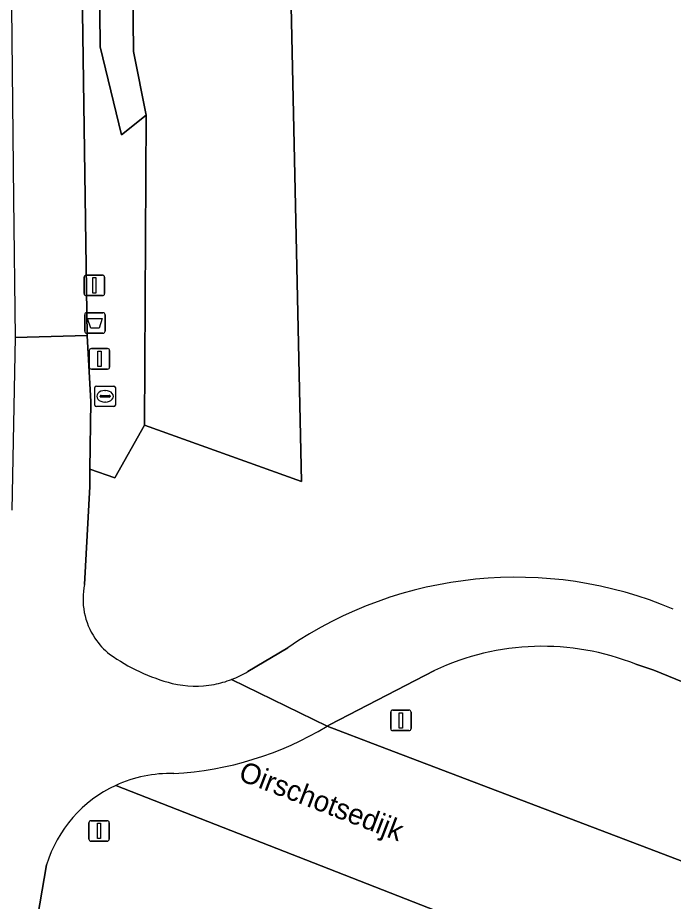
# Model space of a CAD drawing. Extents: x 155209 to 156748, y 385356 to 388487.
# Drawn here: x 155383.28 to 155415.19, y 386855.08 to 386898.09 of the extents above; entities that cross this region are included whole.
import ezdxf

# ---------------------------------------------------------------- set-up
doc = ezdxf.new("R2010")
doc.units = 0
for name, color, linetype in [('IMGEO_Afvalbak', 7, 'Continuous'), ('IMGEO_Berm_groen', 7, 'Continuous'), ('IMGEO_Fietspad_gesloten', 7, 'Continuous'), ('IMGEO_Groenvoorziening', 7, 'Continuous'), ('IMGEO_Lichtmast', 7, 'Continuous'), ('IMGEO_Openbare_ruimte_label', 7, 'Continuous'), ('IMGEO_Rijbaan_lokaal_gesloten', 7, 'Continuous'), ('IMGEO_Rioolput', 7, 'Continuous'), ('IMGEO_Verkeersbordpaal', 7, 'Continuous'), ('IMGEO_Waterloop', 7, 'Continuous')]:
    doc.layers.add(name, color=color, linetype=linetype)

msp = doc.modelspace()

# ---------------------------------------------------------------- linework, layer by layer
at = {"layer": 'IMGEO_Afvalbak'}
for p, q in [((155386.544, 386882.829), (155386.544, 386883.629)), ((155386.544, 386883.629), (155386.544, 386882.829)), ((155386.644, 386883.729), (155387.434, 386883.729)), ((155387.434, 386883.729), (155386.644, 386883.729)), ((155387.534, 386883.629), (155387.534, 386882.829)), ((155387.534, 386882.829), (155387.534, 386883.629)), ((155387.434, 386882.729), (155386.644, 386882.729)), ((155386.644, 386882.729), (155387.434, 386882.729))]:
    msp.add_line(p, q, dxfattribs=at)
msp.add_lwpolyline([(155386.687, 386883.443), (155387.391, 386883.443), (155387.242, 386882.973), (155386.836, 386882.973), (155386.687, 386883.443)], dxfattribs=at)
for centre, start, end in [((155386.644, 386883.629), 90, 180), ((155386.644, 386883.629), 90, 180), ((155387.434, 386883.629), 0, 90), ((155387.434, 386883.629), 360, 90), ((155386.644, 386882.829), 180, 270), ((155386.644, 386882.829), 180, 270), ((155387.434, 386882.829), 270, 0), ((155387.434, 386882.829), 270, 0)]:
    msp.add_arc(centre, 0.1, start, end, dxfattribs=at)
at = {"layer": 'IMGEO_Berm_groen'}
for points in [[(155418.719, 386864.507), (155414.232, 386866.333), (155413.361, 386866.621)], [(155403.572, 386866.316), (155398.462, 386863.678), (155398.335, 386863.601), (155400.892, 386862.631), (155414.712, 386857.387), (155445.113, 386845.774), (155457.912, 386840.913), (155464.072, 386841.781), (155467.301, 386844.699)]]:
    msp.add_lwpolyline(points, dxfattribs=at)
msp.add_arc((155408.816, 386855.242), 12.253, 68.2278, 115.3414, dxfattribs=at)
at = {"layer": 'IMGEO_Fietspad_gesloten'}
for points in [[(155382.435, 386951.848), (155382.988, 386898.593), (155383.085, 386889.277), (155383.155, 386882.53), (155386.663, 386882.616), (155385.603, 386955.738)], [(155386.535, 386870.503), (155386.79, 386875.274), (155386.801, 386876.114), (155386.843, 386879.394), (155386.663, 386882.616), (155383.155, 386882.53), (155383.002, 386874.113)], [(155396.425, 386867.426), (155394.487, 386866.267)], [(155413.361, 386866.621), (155414.232, 386866.333), (155418.719, 386864.507), (155466.767, 386846.51), (155472.836, 386844.21), (155476.035, 386842.963), (155485.347, 386839.199), (155494.869, 386835.35), (155500, 386833.173), (155528.28, 386821.173), (155542.082, 386815.316), (155582.645, 386799.402), (155644.455, 386774.959), (155657.253, 386770.116), (155663.892, 386767.514), (155664.942, 386770.249), (155650.373, 386775.842), (155597.752, 386796.796), (155542.238, 386818.668), (155529.413, 386824.073)], [(155393.692, 386865.88), (155398.335, 386863.601), (155398.462, 386863.678), (155403.572, 386866.316)], [(155398.335, 386863.601), (155393.692, 386865.88)], [(155383.299, 386848.707), (155384.694, 386856.865)]]:
    msp.add_lwpolyline(points, dxfattribs=at)
for centre, radius, start, end in [((155389.897, 386869.798), 3.435, 168.1555, 213.8152), ((155407.522, 386851.188), 19.668, 67.0661, 124.3484), ((155389.896, 386869.791), 3.43, 213.7329, 231.3216), ((155408.816, 386855.242), 12.253, 68.2278, 115.3414), ((155393.271, 386874.947), 9.583, 234.8348, 255.1048), ((155391.895, 386870.581), 5.033, 290.917, 300.996), ((155391.901, 386870.624), 5.071, 280.6868, 290.6876), ((155391.932, 386870.508), 4.951, 256.8808, 280.5831), ((155389.954, 386877.519), 16.247, 273.2741, 301.0545), ((155390.677, 386855.042), 6.261, 88.1205, 114.7565), ((155390.673, 386855.055), 6.247, 114.7756, 163.16)]:
    msp.add_arc(centre, radius, start, end, dxfattribs=at)
at = {"layer": 'IMGEO_Groenvoorziening'}
for points in [[(155388.32, 386952.733), (155388.915, 386896.442), (155389.537, 386893.35), (155389.459, 386878.251), (155397.089, 386875.516), (155395.168, 386964.319), (155388.717, 386966.803), (155386.235, 386964.989)], [(155536.098, 386910.335), (155534.286, 386910.986), (155527.745, 386913.58), (155523.099, 386915.056), (155395.168, 386964.319), (155397.089, 386875.516), (155389.459, 386878.251), (155388.004, 386875.687), (155386.801, 386876.114), (155386.79, 386875.274), (155386.535, 386870.503)], [(155385.413, 386956.748), (155385.603, 386955.738), (155386.663, 386882.616), (155386.843, 386879.394), (155386.801, 386876.114), (155388.004, 386875.687), (155389.459, 386878.251), (155389.537, 386893.35), (155388.34, 386892.391), (155387.298, 386896.672), (155386.781, 386950.846)], [(155394.487, 386866.267), (155396.425, 386867.426)], [(155394.977, 386847.885), (155396.121, 386848.772), (155399.255, 386850.072), (155401.499, 386850.438), (155406.884, 386849.679), (155433.798, 386839.395), (155443.335, 386836.339), (155453.576, 386832.241), (155454.34, 386830.99), (155455.729, 386830.445), (155457.34, 386833.958), (155453.658, 386835.338), (155447.01, 386837.973), (155422.593, 386847.21), (155388.055, 386860.727)], [(155384.694, 386856.865), (155383.299, 386848.707), (155377.495, 386814.325), (155376.591, 386809.635)]]:
    msp.add_lwpolyline(points, dxfattribs=at)
for centre, radius, start, end in [((155389.897, 386869.798), 3.435, 168.1555, 213.8152), ((155407.522, 386851.188), 19.668, 67.0661, 124.3484), ((155389.896, 386869.791), 3.43, 213.7329, 231.3216), ((155393.271, 386874.947), 9.583, 234.8348, 255.1048), ((155391.895, 386870.581), 5.033, 290.917, 300.996), ((155391.901, 386870.624), 5.071, 280.6868, 290.6876), ((155391.932, 386870.508), 4.951, 256.8808, 280.5831), ((155390.673, 386855.055), 6.247, 114.7756, 163.16)]:
    msp.add_arc(centre, radius, start, end, dxfattribs=at)
at = {"layer": 'IMGEO_Lichtmast'}
for p, q in [((155386.618, 386885.56), (155387.408, 386885.56)), ((155387.408, 386885.56), (155386.618, 386885.56)), ((155386.518, 386884.66), (155386.518, 386885.46)), ((155386.518, 386885.46), (155386.518, 386884.66)), ((155387.508, 386885.46), (155387.508, 386884.66)), ((155387.508, 386884.66), (155387.508, 386885.46)), ((155387.408, 386884.56), (155386.618, 386884.56)), ((155386.618, 386884.56), (155387.408, 386884.56)), ((155401.434, 386863.489), (155401.434, 386864.289)), ((155401.434, 386864.289), (155401.434, 386863.489)), ((155401.534, 386864.389), (155402.324, 386864.389)), ((155402.324, 386864.389), (155401.534, 386864.389)), ((155402.424, 386864.289), (155402.424, 386863.489)), ((155402.424, 386863.489), (155402.424, 386864.289)), ((155402.324, 386863.389), (155401.534, 386863.389)), ((155401.534, 386863.389), (155402.324, 386863.389)), ((155386.747, 386858.109), (155386.747, 386858.909)), ((155386.747, 386858.909), (155386.747, 386858.109)), ((155386.847, 386859.009), (155387.637, 386859.009)), ((155387.637, 386859.009), (155386.847, 386859.009)), ((155387.737, 386858.909), (155387.737, 386858.109)), ((155387.737, 386858.109), (155387.737, 386858.909)), ((155387.637, 386858.009), (155386.847, 386858.009)), ((155386.847, 386858.009), (155387.637, 386858.009))]:
    msp.add_line(p, q, dxfattribs=at)
for points in [[(155386.938, 386885.435), (155387.088, 386885.435), (155387.088, 386884.685), (155386.938, 386884.685), (155386.938, 386885.435)], [(155401.854, 386864.264), (155402.004, 386864.264), (155402.004, 386863.514), (155401.854, 386863.514), (155401.854, 386864.264)], [(155387.167, 386858.884), (155387.317, 386858.884), (155387.317, 386858.134), (155387.167, 386858.134), (155387.167, 386858.884)]]:
    msp.add_lwpolyline(points, dxfattribs=at)
for centre, start, end in [((155386.618, 386885.46), 90, 180), ((155386.618, 386885.46), 90, 180), ((155387.408, 386885.46), 0, 90), ((155387.408, 386885.46), 360, 90), ((155386.618, 386884.66), 180, 270), ((155386.618, 386884.66), 180, 270), ((155387.408, 386884.66), 270, 0), ((155387.408, 386884.66), 270, 0), ((155401.534, 386864.289), 90, 180), ((155401.534, 386864.289), 90, 180), ((155402.324, 386864.289), 0, 90), ((155402.324, 386864.289), 360, 90), ((155401.534, 386863.489), 180, 270), ((155401.534, 386863.489), 180, 270), ((155402.324, 386863.489), 270, 0), ((155402.324, 386863.489), 270, 0), ((155386.847, 386858.909), 90, 180), ((155386.847, 386858.909), 90, 180), ((155387.637, 386858.909), 0, 90), ((155387.637, 386858.909), 360, 90), ((155386.847, 386858.109), 180, 270), ((155386.847, 386858.109), 180, 270), ((155387.637, 386858.109), 270, 0), ((155387.637, 386858.109), 270, 0)]:
    msp.add_arc(centre, 0.1, start, end, dxfattribs=at)
at = {"layer": 'IMGEO_Rijbaan_lokaal_gesloten'}
for points in [[(155525.795, 386814.806), (155508.895, 386821.379), (155500, 386824.799), (155498.716, 386825.292), (155471.872, 386835.612), (155457.912, 386840.913), (155445.113, 386845.774), (155414.712, 386857.387), (155400.892, 386862.631), (155398.335, 386863.601)], [(155388.055, 386860.727), (155422.593, 386847.21), (155447.01, 386837.973), (155453.658, 386835.338), (155457.34, 386833.958), (155460.364, 386832.826), (155464.215, 386831.235), (155478.143, 386825.817), (155496.809, 386818.679), (155500, 386817.426), (155523.256, 386808.297), (155617.562, 386771.277), (155634.604, 386764.62)]]:
    msp.add_lwpolyline(points, dxfattribs=at)
for centre, radius, start, end in [((155389.954, 386877.519), 16.247, 273.2741, 301.0545), ((155390.677, 386855.042), 6.261, 88.1205, 114.7565)]:
    msp.add_arc(centre, radius, start, end, dxfattribs=at)
at = {"layer": 'IMGEO_Rioolput'}
for p, q in [((155387.038, 386879.235), (155387.038, 386880.087)), ((155387.113, 386880.161), (155387.965, 386880.161)), ((155387.526, 386879.941), (155387.551, 386879.941)), ((155388.039, 386880.087), (155388.039, 386879.235)), ((155387.297, 386879.655), (155387.297, 386879.667)), ((155387.735, 386879.618), (155387.337, 386879.618)), ((155387.34, 386879.704), (155387.738, 386879.704)), ((155387.781, 386879.667), (155387.781, 386879.655)), ((155387.965, 386879.161), (155387.113, 386879.161)), ((155387.549, 386879.381), (155387.524, 386879.381))]:
    msp.add_line(p, q, dxfattribs=at)
for points in [[(155387.038, 386879.235), (155387.038, 386880.087)], [(155387.113, 386880.161), (155387.965, 386880.161)], [(155388.039, 386880.087), (155388.039, 386879.235)], [(155387.965, 386879.161), (155387.113, 386879.161)]]:
    msp.add_lwpolyline(points, dxfattribs=at)
for centre, radius, start, end in [((155387.115, 386880.085), 0.0765, 91.552, 178.448), ((155387.115, 386880.085), 0.0765, 91.552, 178.448), ((155387.963, 386880.085), 0.0765, 1.552, 88.448), ((155387.963, 386880.085), 0.0765, 1.552, 88.448), ((155387.337, 386879.664), 0.0403, 85.8775, 175.7526), ((155387.334, 386879.654), 0.0366, 178.938, 274.7102), ((155387.738, 386879.661), 0.043, 264.8664, 352.4533), ((155387.742, 386879.666), 0.0386, 1.7309, 96.639), ((155387.115, 386879.237), 0.0765, 181.552, 268.448), ((155387.115, 386879.237), 0.0765, 181.552, 268.448), ((155387.963, 386879.237), 0.0765, 271.552, 358.448), ((155387.963, 386879.237), 0.0765, 271.552, 358.448)]:
    msp.add_arc(centre, radius, start, end, dxfattribs=at)
for centre, major_axis, ratio, start_param, end_param in [((155387.525, 386879.661), (-0.387, 0.002), 0.722429, 4.712389, 7.853982), ((155387.55, 386879.661), (-0.39, 0.002), 0.717154, 1.570796, 4.712389)]:
    msp.add_ellipse(centre, major_axis=major_axis, ratio=ratio, start_param=start_param, end_param=end_param, dxfattribs=at)
at = {"layer": 'IMGEO_Verkeersbordpaal'}
for p, q in [((155386.768, 386881.083), (155386.768, 386881.883)), ((155386.768, 386881.883), (155386.768, 386881.083)), ((155386.868, 386881.983), (155387.658, 386881.983)), ((155387.658, 386881.983), (155386.868, 386881.983)), ((155387.758, 386881.883), (155387.758, 386881.083)), ((155387.758, 386881.083), (155387.758, 386881.883)), ((155387.658, 386880.983), (155386.868, 386880.983)), ((155386.868, 386880.983), (155387.658, 386880.983))]:
    msp.add_line(p, q, dxfattribs=at)
msp.add_lwpolyline([(155387.188, 386881.858), (155387.338, 386881.858), (155387.338, 386881.108), (155387.188, 386881.108), (155387.188, 386881.858)], dxfattribs=at)
for centre, start, end in [((155386.868, 386881.883), 90, 180), ((155386.868, 386881.883), 90, 180), ((155387.658, 386881.883), 0, 90), ((155387.658, 386881.883), 360, 90), ((155386.868, 386881.083), 180, 270), ((155386.868, 386881.083), 180, 270), ((155387.658, 386881.083), 270, 0), ((155387.658, 386881.083), 270, 0)]:
    msp.add_arc(centre, 0.1, start, end, dxfattribs=at)
at = {"layer": 'IMGEO_Waterloop'}
msp.add_lwpolyline([(155386.781, 386950.846), (155387.298, 386896.672), (155388.34, 386892.391), (155389.537, 386893.35), (155388.915, 386896.442), (155388.32, 386952.733)], dxfattribs=at)

# ---------------------------------------------------------------- texts
at = {"layer": 'IMGEO_Openbare_ruimte_label'}
msp.add_text('Oirschotsedijk', height=1, rotation=339.0283, dxfattribs=at).set_placement((155393.971, 386861.002))

doc.saveas('drawing.dxf')
